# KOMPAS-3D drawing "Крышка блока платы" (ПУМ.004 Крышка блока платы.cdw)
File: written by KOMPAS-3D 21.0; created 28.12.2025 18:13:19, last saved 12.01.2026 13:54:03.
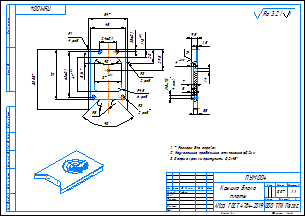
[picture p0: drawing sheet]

Sheet 1: A4x2, landscape

Document properties: Автор: Гузель; Знак неуказанной шероховатости: 4; Параметр неуказанной шероховатости: Ra 3.2; Масса: 0.073379; Форматы листов документа: A4@4~2

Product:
- Part/product: Крышка блока платы
    Материал: АМг6  ГОСТ 4784-2019 (density 2650 kg/m3)
    Масса: 0.073379

Title block, sheet 1: Наименование: Крышка блока / платы; designation: ПУМ.004; Материал: АМг6  ГОСТ 4784-2019; Масса: 0,07; Количество листов документа: 1; organisation: ООО ТПК Пегас; Форматы листов документа: A4 2; stored path: C:\Users\User\Desktop\ПУ\ПУМ\Чертежи\ПУМ.004 Крышка блока платы.cdw; Разработал: Гайсин

Views: Вид 1, Снизу, Проекционный вид 2, Местный разрез 1, Местный разрез 2
Referenced files in C:\Users\Гузель\Desktop\ПУМ\: ПУМ.004 Крышка блока платы.m3d
Referenced files in C:\Users\User\Desktop\ПУ\ПУМ\: ПУМ.004 Крышка блока платы.m3d
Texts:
  Ra 3.2
  Ra 3.2 ( )
Dimensions and other numbers on the sheet: 83,58; 54; 24±0,1; 37; 11,5; 47; 4,5; 6 рад; 8,16; 3; 2 рад; 3,5±0,1; 63±0,1; 70; 1; 4 рад; 20; 5; 48; 29,5; 9,5; 1,5; 4; 7; -7Н; 4 отв; 5,5; 1,6; 1:1; 0,07

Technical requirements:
  * Размеры для справок
  Неуказанные предельные отклонения  0,2мм
  Острые кромки притупить 0,2х45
